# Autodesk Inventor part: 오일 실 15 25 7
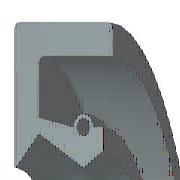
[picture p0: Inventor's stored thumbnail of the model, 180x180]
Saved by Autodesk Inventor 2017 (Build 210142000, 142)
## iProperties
Created: 2012-02
Part Number: 오일 실 15 25 7
Material: 고무
Description: 오일-실
Document SubType Name: Modeling
Standard: KS B 2804
Designer: mduedu
Standards Organization: KS
Language: ko-KR
Size Designation: D - 15 25 7
Categories: <MemberInstance><Categories><Category DisplayName="샤프트 부품" InternalName="7f7aeb1f-a693-4053-b835-cee3144e0d98" Mnemonic="SHFT"><Category DisplayName="실링" Intern
Density: 0.93 g/cm^3
Appearance: 고무 - 검은색 - 버전 1.1
IsCustomPart: 1
Author: mduedu
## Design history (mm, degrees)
revolve "본체" stored, may be unused: angle "d17" = 90 deg
revolve "스프링1" stored, may be unused: angle "d18" = 90 deg
body "Solid1"
sketch "스케치1"
  geometry: L1 (0, 12.5)-(7, 12.5); L2 (7, 10.75)-(1.75, 10.75); L3 (1.75, 9.25)-(4.9, 7.5); L4 (4.9, 7.5)-(0, 7.5); L5 (0, 0)-(9.586, 0) reference; L6 (4.9, 7.5)-(6.3, 8.375); L7 (0, 18)-(0, -3) reference; L8 (-1.941, 0)-(11.507, 0) reference; L9 (4.2, 9.6)-(1.75, 10.09); L10 (1.75, 10.09)-(1.75, 10.75); L11 (0, 12.5)-(0, 7.588); L12 (4.9, 7.5)-(0, 7.5); L13 (1.75, 9.25)-(0.152, 7.528); L14 (7, 12.5)-(7, 10.75); L15 (5.6, 9.6)-(6.3, 9.6); L16 (6.3, 9.6)-(6.3, 8.375); C1 r 0.455 at (4.9, 9.6); A1 r 0.7 centre (4.9, 9.6) between (5.6, 9.6) and (4.2, 9.6); A2 r 0.088 centre (0.088, 7.588) between (0, 7.588) and (0.152, 7.528); 1 further point
  constraints: 28 end point, 5 horizontal alignment, 5 point on line, 4 point on circle, 4 vertical alignment, 3 centre point, 3 tangent, 2 collinear, 2 horizontal, 2 perpendicular, 1 coincident, 1 parallel
  dimensions: "d0" = 25 diameter of L1 L5 (= SD2); "d1" = 1.75 distance of L1.end L2.start (= SD); "d2" = 0.91 diameter of C1 (= SPDI); "d3" = 1.4 diameter of A1 (= SPDA); "d4" = 15 diameter of L3.end L5 (= NND); "d5" = 18.5 diameter of L3.start L5 (= TKDM); "d7" = 20.18 diameter of L9.end L5 (= TKDM + 0.24 x SWDT); "d8" = 1.75 distance between parallel lines of L11 L10 (= SD); "d9" = 4.9 distance from line of L11 C1.centre (= SPDST); "d10" = 19.2 diameter of C1.centre L5 (= HLDM); "d11" = 0.0875 radius of A2 (= 0.25 x LAB); "d12" = 6.3 distance between parallel lines of L11 L16 (= SDI); "d13" = 16.75 diameter of L6.end L5 (= ABDM); "d14" = 7 distance from line of L11 L1.end (= SWDT)
fillet "모깎기1" dims "d6" = 0.3 (= RR)
other parameters: "SD2" = 25 [user parameter; used in 1 equation term], "SWDT" = 7 [user parameter; used in 2 equation terms], "RR" = 0.3 [user parameter; used in 1 equation term], "SD" = 1.75 [user parameter; used in 2 equation terms], "NND" = 15 [user parameter; used in 1 equation term], "SPDA" = 1.4 [user parameter; used in 1 equation term], "SPDI" = 0.91 [user parameter; used in 1 equation term], "TKDM" = 18.5 [user parameter; used in 2 equation terms], "HLDM" = 19.2 [user parameter; used in 1 equation term], "ABDM" = 16.75 [user parameter; used in 1 equation term], "SDI" = 6.3 [user parameter; used in 1 equation term], "SPDST" = 4.9 [user parameter; used in 1 equation term], "LAB" = 0.35 [user parameter; used in 1 equation term], "d15" = 0, "d16" = 0, "d19" = 0
